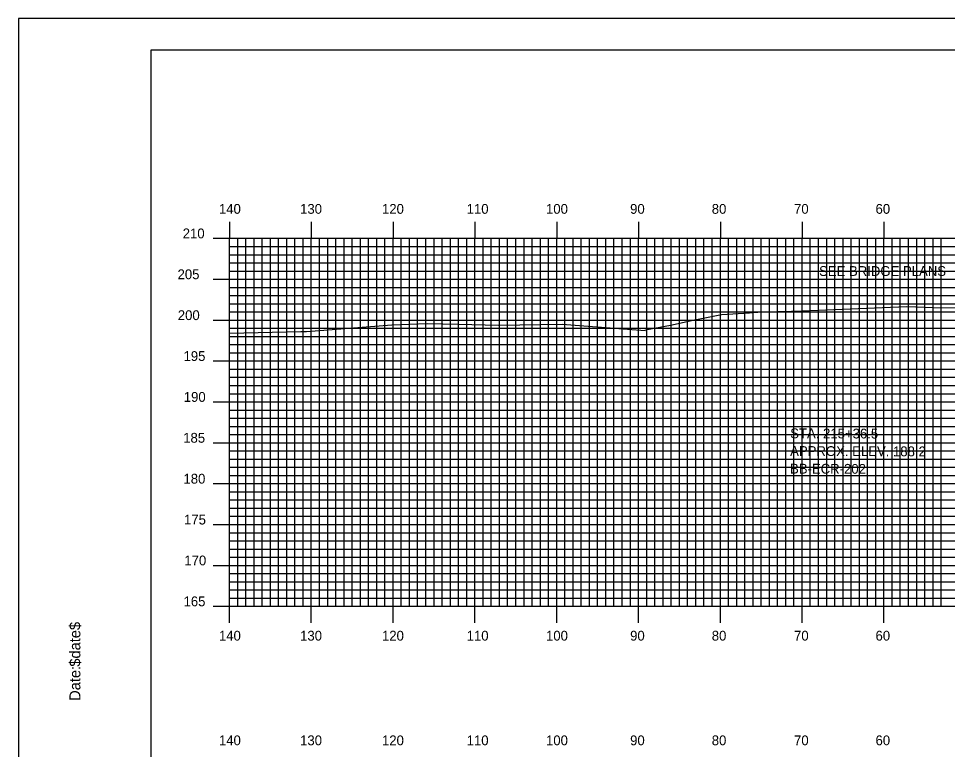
# Model space of a CAD drawing. Extents: x 1796027 to 1796370, y 442591 to 442811.
# Drawn here: x 1796026.6 to 1796140.1, y 442721.2 to 442810.5 of the extents above; entities that cross this region are included whole.
import ezdxf

# ---------------------------------------------------------------- set-up
doc = ezdxf.new("R2010")
doc.units = 0
for name, color, linetype in [('ANNOTATION', 7, 'Continuous'), ('BORDER', 7, 'Continuous'), ('BORING - REFUSAL', 7, 'Continuous'), ('H_V ANNOTATION', 7, 'Continuous'), ('MAJOR', 7, 'Continuous'), ('MINOR', 7, 'Continuous'), ('PLOT BOUNDARY', 7, 'Continuous'), ('S_Roadway_Centerline', 7, 'Continuous')]:
    doc.layers.add(name, color=color, linetype=linetype)

msp = doc.modelspace()

# ---------------------------------------------------------------- linework, layer by layer
at = {"layer": 'BORDER'}
msp.add_lwpolyline([(1796042.79, 442596.67), (1796362.79, 442596.67), (1796362.79, 442806.67), (1796042.79, 442806.67)], close=True, dxfattribs=at)
at = {"layer": 'MAJOR'}
for p, q in [((1796052.39, 442785.67), (1796052.39, 442783.67)), ((1796062.39, 442785.67), (1796062.39, 442783.67)), ((1796072.39, 442785.67), (1796072.39, 442783.67)), ((1796082.39, 442785.67), (1796082.39, 442783.67)), ((1796092.39, 442785.67), (1796092.39, 442783.67)), ((1796102.39, 442785.67), (1796102.39, 442783.67)), ((1796112.39, 442785.67), (1796112.39, 442783.67)), ((1796122.39, 442785.67), (1796122.39, 442783.67)), ((1796132.39, 442785.67), (1796132.39, 442783.67)), ((1796050.39, 442783.67), (1796052.39, 442783.67)), ((1796052.39, 442783.67), (1796332.39, 442783.67)), ((1796052.39, 442738.67), (1796052.39, 442783.67)), ((1796052.39, 442738.67), (1796052.39, 442783.67)), ((1796052.39, 442783.67), (1796332.39, 442783.67)), ((1796062.39, 442738.67), (1796062.39, 442783.67)), ((1796072.39, 442738.67), (1796072.39, 442783.67)), ((1796082.39, 442738.67), (1796082.39, 442783.67)), ((1796092.39, 442738.67), (1796092.39, 442783.67)), ((1796102.39, 442738.67), (1796102.39, 442783.67)), ((1796112.39, 442738.67), (1796112.39, 442783.67)), ((1796122.39, 442738.67), (1796122.39, 442783.67)), ((1796132.39, 442738.67), (1796132.39, 442783.67)), ((1796050.39, 442778.67), (1796052.39, 442778.67)), ((1796052.39, 442778.67), (1796332.39, 442778.67)), ((1796050.39, 442773.67), (1796052.39, 442773.67)), ((1796052.39, 442773.67), (1796332.39, 442773.67)), ((1796050.39, 442768.67), (1796052.39, 442768.67)), ((1796052.39, 442768.67), (1796332.39, 442768.67)), ((1796050.39, 442763.67), (1796052.39, 442763.67)), ((1796052.39, 442763.67), (1796332.39, 442763.67)), ((1796050.39, 442758.67), (1796052.39, 442758.67)), ((1796052.39, 442758.67), (1796332.39, 442758.67)), ((1796050.39, 442753.67), (1796052.39, 442753.67)), ((1796052.39, 442753.67), (1796332.39, 442753.67)), ((1796050.39, 442748.67), (1796052.39, 442748.67)), ((1796052.39, 442748.67), (1796332.39, 442748.67)), ((1796050.39, 442743.67), (1796052.39, 442743.67)), ((1796052.39, 442743.67), (1796332.39, 442743.67)), ((1796050.39, 442738.67), (1796052.39, 442738.67)), ((1796052.39, 442738.67), (1796332.39, 442738.67)), ((1796052.39, 442738.67), (1796332.39, 442738.67)), ((1796052.39, 442736.66), (1796052.39, 442738.67)), ((1796062.39, 442736.66), (1796062.39, 442738.67)), ((1796072.39, 442736.66), (1796072.39, 442738.67)), ((1796082.39, 442736.66), (1796082.39, 442738.67)), ((1796092.39, 442736.66), (1796092.39, 442738.67)), ((1796102.39, 442736.66), (1796102.39, 442738.67)), ((1796112.39, 442736.66), (1796112.39, 442738.67)), ((1796122.39, 442736.66), (1796122.39, 442738.67)), ((1796132.39, 442736.66), (1796132.39, 442738.67))]:
    msp.add_line(p, q, dxfattribs=at)
at = {"layer": 'MINOR'}
for p, q in [((1796053.39, 442738.67), (1796053.39, 442783.67)), ((1796054.39, 442738.67), (1796054.39, 442783.67)), ((1796055.39, 442738.67), (1796055.39, 442783.67)), ((1796056.39, 442738.67), (1796056.39, 442783.67)), ((1796057.39, 442738.67), (1796057.39, 442783.67)), ((1796058.39, 442738.67), (1796058.39, 442783.67)), ((1796059.39, 442738.67), (1796059.39, 442783.67)), ((1796060.39, 442738.67), (1796060.39, 442783.67)), ((1796061.39, 442738.67), (1796061.39, 442783.67)), ((1796063.39, 442738.67), (1796063.39, 442783.67)), ((1796064.39, 442738.67), (1796064.39, 442783.67)), ((1796065.39, 442738.67), (1796065.39, 442783.67)), ((1796066.39, 442738.67), (1796066.39, 442783.67)), ((1796067.39, 442738.67), (1796067.39, 442783.67)), ((1796068.39, 442738.67), (1796068.39, 442783.67)), ((1796069.39, 442738.67), (1796069.39, 442783.67)), ((1796070.39, 442738.67), (1796070.39, 442783.67)), ((1796071.39, 442738.67), (1796071.39, 442783.67)), ((1796073.39, 442738.67), (1796073.39, 442783.67)), ((1796074.39, 442738.67), (1796074.39, 442783.67)), ((1796075.39, 442738.67), (1796075.39, 442783.67)), ((1796076.39, 442738.67), (1796076.39, 442783.67)), ((1796077.39, 442738.67), (1796077.39, 442783.67)), ((1796078.39, 442738.67), (1796078.39, 442783.67)), ((1796079.39, 442738.67), (1796079.39, 442783.67)), ((1796080.39, 442738.67), (1796080.39, 442783.67)), ((1796081.39, 442738.67), (1796081.39, 442783.67)), ((1796083.39, 442738.67), (1796083.39, 442783.67)), ((1796084.39, 442738.67), (1796084.39, 442783.67)), ((1796085.39, 442738.67), (1796085.39, 442783.67)), ((1796086.39, 442738.67), (1796086.39, 442783.67)), ((1796087.39, 442738.67), (1796087.39, 442783.67)), ((1796088.39, 442738.67), (1796088.39, 442783.67)), ((1796089.39, 442738.67), (1796089.39, 442783.67)), ((1796090.39, 442738.67), (1796090.39, 442783.67)), ((1796091.39, 442738.67), (1796091.39, 442783.67)), ((1796093.39, 442738.67), (1796093.39, 442783.67)), ((1796094.39, 442738.67), (1796094.39, 442783.67)), ((1796095.39, 442738.67), (1796095.39, 442783.67)), ((1796096.39, 442738.67), (1796096.39, 442783.67)), ((1796097.39, 442738.67), (1796097.39, 442783.67)), ((1796098.39, 442738.67), (1796098.39, 442783.67)), ((1796099.39, 442738.67), (1796099.39, 442783.67)), ((1796100.39, 442738.67), (1796100.39, 442783.67)), ((1796101.39, 442738.67), (1796101.39, 442783.67)), ((1796103.39, 442738.67), (1796103.39, 442783.67)), ((1796104.39, 442738.67), (1796104.39, 442783.67)), ((1796105.39, 442738.67), (1796105.39, 442783.67)), ((1796106.39, 442738.67), (1796106.39, 442783.67)), ((1796107.39, 442738.67), (1796107.39, 442783.67)), ((1796108.39, 442738.67), (1796108.39, 442783.67)), ((1796109.39, 442738.67), (1796109.39, 442783.67)), ((1796110.39, 442738.67), (1796110.39, 442783.67)), ((1796111.39, 442738.67), (1796111.39, 442783.67)), ((1796113.39, 442738.67), (1796113.39, 442783.67)), ((1796114.39, 442738.67), (1796114.39, 442783.67)), ((1796115.39, 442738.67), (1796115.39, 442783.67)), ((1796116.39, 442738.67), (1796116.39, 442783.67)), ((1796117.39, 442738.67), (1796117.39, 442783.67)), ((1796118.39, 442738.67), (1796118.39, 442783.67)), ((1796119.39, 442738.67), (1796119.39, 442783.67)), ((1796120.39, 442738.67), (1796120.39, 442783.67)), ((1796121.39, 442738.67), (1796121.39, 442783.67)), ((1796123.39, 442738.67), (1796123.39, 442783.67)), ((1796124.39, 442738.67), (1796124.39, 442783.67)), ((1796125.39, 442738.67), (1796125.39, 442783.67)), ((1796126.39, 442738.67), (1796126.39, 442783.67)), ((1796127.39, 442738.67), (1796127.39, 442783.67)), ((1796128.39, 442738.67), (1796128.39, 442783.67)), ((1796129.39, 442738.67), (1796129.39, 442783.67)), ((1796130.39, 442738.67), (1796130.39, 442783.67)), ((1796131.39, 442738.67), (1796131.39, 442783.67)), ((1796133.39, 442738.67), (1796133.39, 442783.67)), ((1796134.39, 442738.67), (1796134.39, 442783.67)), ((1796135.39, 442738.67), (1796135.39, 442783.67)), ((1796136.39, 442738.67), (1796136.39, 442783.67)), ((1796137.39, 442738.67), (1796137.39, 442783.67)), ((1796138.39, 442738.67), (1796138.39, 442783.67)), ((1796139.39, 442738.67), (1796139.39, 442783.67)), ((1796052.39, 442782.67), (1796332.39, 442782.67)), ((1796052.39, 442782.67), (1796054.4, 442782.67)), ((1796052.39, 442781.67), (1796332.39, 442781.67)), ((1796052.39, 442781.67), (1796054.4, 442781.67)), ((1796052.39, 442780.67), (1796332.39, 442780.67)), ((1796052.39, 442780.67), (1796054.4, 442780.67)), ((1796052.39, 442779.67), (1796332.39, 442779.67)), ((1796052.39, 442779.67), (1796054.4, 442779.67)), ((1796052.39, 442777.67), (1796332.39, 442777.67)), ((1796052.39, 442777.67), (1796054.4, 442777.67)), ((1796052.39, 442776.67), (1796332.39, 442776.67)), ((1796052.39, 442776.67), (1796054.4, 442776.67)), ((1796052.39, 442775.67), (1796332.39, 442775.67)), ((1796052.39, 442775.67), (1796054.4, 442775.67)), ((1796052.39, 442774.67), (1796332.39, 442774.67)), ((1796052.39, 442774.67), (1796054.4, 442774.67)), ((1796052.39, 442772.67), (1796332.39, 442772.67)), ((1796052.39, 442772.67), (1796054.4, 442772.67)), ((1796052.39, 442771.67), (1796332.39, 442771.67)), ((1796052.39, 442771.67), (1796054.4, 442771.67)), ((1796052.39, 442770.67), (1796332.39, 442770.67)), ((1796052.39, 442770.67), (1796054.4, 442770.67)), ((1796052.39, 442769.67), (1796332.39, 442769.67)), ((1796052.39, 442769.67), (1796054.4, 442769.67)), ((1796052.39, 442767.67), (1796332.39, 442767.67)), ((1796052.39, 442767.67), (1796054.4, 442767.67)), ((1796052.39, 442766.67), (1796332.39, 442766.67)), ((1796052.39, 442766.67), (1796054.4, 442766.67)), ((1796052.39, 442765.67), (1796332.39, 442765.67)), ((1796052.39, 442765.67), (1796054.4, 442765.67)), ((1796052.39, 442764.67), (1796332.39, 442764.67)), ((1796052.39, 442764.67), (1796054.4, 442764.67)), ((1796052.39, 442762.67), (1796332.39, 442762.67)), ((1796052.39, 442762.67), (1796054.4, 442762.67)), ((1796052.39, 442761.67), (1796332.39, 442761.67)), ((1796052.39, 442761.67), (1796054.4, 442761.67)), ((1796052.39, 442760.67), (1796332.39, 442760.67)), ((1796052.39, 442760.67), (1796054.4, 442760.67)), ((1796052.39, 442759.67), (1796332.39, 442759.67)), ((1796052.39, 442759.67), (1796054.4, 442759.67)), ((1796052.39, 442757.67), (1796332.39, 442757.67)), ((1796052.39, 442757.67), (1796054.4, 442757.67)), ((1796052.39, 442756.67), (1796332.39, 442756.67)), ((1796052.39, 442756.67), (1796054.4, 442756.67)), ((1796052.39, 442755.67), (1796332.39, 442755.67)), ((1796052.39, 442755.67), (1796054.4, 442755.67)), ((1796052.39, 442754.67), (1796332.39, 442754.67)), ((1796052.39, 442754.67), (1796054.4, 442754.67)), ((1796052.39, 442752.67), (1796332.39, 442752.67)), ((1796052.39, 442752.67), (1796054.4, 442752.67)), ((1796052.39, 442751.67), (1796332.39, 442751.67)), ((1796052.39, 442751.67), (1796054.4, 442751.67)), ((1796052.39, 442750.67), (1796332.39, 442750.67)), ((1796052.39, 442750.67), (1796054.4, 442750.67)), ((1796052.39, 442749.67), (1796332.39, 442749.67)), ((1796052.39, 442749.67), (1796054.4, 442749.67)), ((1796052.39, 442747.67), (1796332.39, 442747.67)), ((1796052.39, 442747.67), (1796054.4, 442747.67)), ((1796052.39, 442746.67), (1796332.39, 442746.67)), ((1796052.39, 442746.67), (1796054.4, 442746.67)), ((1796052.39, 442745.67), (1796332.39, 442745.67)), ((1796052.39, 442745.67), (1796054.4, 442745.67)), ((1796052.39, 442744.67), (1796332.39, 442744.67)), ((1796052.39, 442744.67), (1796054.4, 442744.67)), ((1796052.39, 442742.67), (1796332.39, 442742.67)), ((1796052.39, 442742.67), (1796054.4, 442742.67)), ((1796052.39, 442741.67), (1796332.39, 442741.67)), ((1796052.39, 442741.67), (1796054.4, 442741.67)), ((1796052.39, 442740.67), (1796332.39, 442740.67)), ((1796052.39, 442740.67), (1796054.4, 442740.67)), ((1796052.39, 442739.67), (1796332.39, 442739.67)), ((1796052.39, 442739.67), (1796054.4, 442739.67))]:
    msp.add_line(p, q, dxfattribs=at)
at = {"layer": 'PLOT BOUNDARY'}
msp.add_lwpolyline([(1796026.61, 442590.55), (1796366.61, 442590.55), (1796366.61, 442810.55), (1796026.61, 442810.55)], close=True, dxfattribs=at)
at = {"layer": 'S_Roadway_Centerline'}
msp.add_lwpolyline([(1796052.39, 442772.08), (1796061.12, 442772.27), (1796061.53, 442772.28), (1796061.81, 442772.28), (1796062.87, 442772.36), (1796072.23, 442773.09), (1796076.54, 442773.24), (1796080.4, 442773.17), (1796085.27, 442773.03), (1796093.05, 442773.19), (1796101.06, 442772.56), (1796103.22, 442772.38), (1796103.26, 442772.49), (1796106.3, 442773.05), (1796109.43, 442773.76), (1796109.69, 442773.8), (1796112.55, 442774.35), (1796115.97, 442774.56), (1796116.96, 442774.63), (1796117.7, 442774.69), (1796121.1, 442774.77), (1796121.3, 442774.77), (1796121.35, 442774.78), (1796135.19, 442775.32), (1796138.46, 442775.22), (1796141.12, 442775.15)], dxfattribs=at)

# ---------------------------------------------------------------- texts
at = {"layer": 'ANNOTATION'}
msp.add_text('SEE BRIDGE PLANS', height=1.2, dxfattribs=at).set_placement((1796124.46, 442779.07))
at = {"layer": 'BORDER'}
for s, p in [('$date$', (1796034.16, 442731.28)), ('Date:', (1796034.16, 442727.1))]:
    msp.add_text(s, height=1.339, rotation=90, dxfattribs=at).set_placement(p)
at = {"layer": 'BORING - REFUSAL'}
for s, p in [('STA. 215+36.5', (1796120.93, 442759.22)), ('APPROX. ELEV. 188.2', (1796120.92, 442757.06)), ('BB-ECR-202', (1796120.91, 442754.9))]:
    msp.add_text(s, height=1.2, rotation=359.8142, dxfattribs=at).set_placement(p)
at = {"layer": 'H_V ANNOTATION'}
for s, p in [('140', (1796051.1, 442786.67)), ('130', (1796061.02, 442786.67)), ('120', (1796071.03, 442786.67)), ('110', (1796081.38, 442786.67)), ('100', (1796091.08, 442786.67)), ('90', (1796101.36, 442786.67)), ('80', (1796111.34, 442786.67)), ('70', (1796121.4, 442786.67)), ('60', (1796131.36, 442786.67)), ('210', (1796046.67, 442783.67)), ('205', (1796046.04, 442778.67)), ('200', (1796046.07, 442773.67)), ('195', (1796046.77, 442768.67)), ('190', (1796046.8, 442763.67)), ('185', (1796046.73, 442758.67)), ('180', (1796046.76, 442753.67)), ('175', (1796046.83, 442748.67)), ('170', (1796046.87, 442743.67)), ('165', (1796046.77, 442738.67)), ('140', (1796051.1, 442734.47)), ('130', (1796061.02, 442734.47)), ('120', (1796071.03, 442734.47)), ('110', (1796081.38, 442734.47)), ('100', (1796091.08, 442734.47)), ('90', (1796101.36, 442734.47)), ('80', (1796111.34, 442734.47)), ('70', (1796121.4, 442734.47)), ('60', (1796131.36, 442734.47)), ('140', (1796051.1, 442721.67)), ('130', (1796061.02, 442721.67)), ('120', (1796071.03, 442721.67)), ('110', (1796081.38, 442721.67)), ('100', (1796091.08, 442721.67)), ('90', (1796101.36, 442721.67)), ('80', (1796111.34, 442721.67)), ('70', (1796121.4, 442721.67)), ('60', (1796131.36, 442721.67))]:
    msp.add_text(s, height=1.2, dxfattribs=at).set_placement(p)
at = {"layer": 'MAJOR'}
msp.add_text('-', height=0.012, dxfattribs=at).set_placement((1796052.38, 442738.67))
at = {"layer": 'S_Roadway_Centerline'}
for s, p in [('C', (1796135.18, 442775.32)), ('C', (1796135.18, 442775.32)), ('L', (1796135.19, 442775.31)), ('L', (1796135.19, 442775.31))]:
    msp.add_text(s, height=0.0146, dxfattribs=at).set_placement(p)

doc.saveas('drawing.dxf')
